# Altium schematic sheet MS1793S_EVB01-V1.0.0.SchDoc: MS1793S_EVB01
size A4; Date: 2018-06-01; Author: Wang QB; Revision: V1.0; SheetNumber: 1; SheetTotal: 1; PageSetup: Record=PageOptions¦CenterHorizontal=True¦CenterVertical=True¦PrintScale=1.00¦XCorrection=1.00¦YCorrection=1.00¦PrintKind=0¦BorderSize=5000000¦LeftOffset=0¦BottomOffset=0¦Orientation=2¦PaperLength=1000¦PaperWidth=1000¦Scale=100¦PaperSource=7¦PrintQuality=-3¦MediaType=1¦DitherType=10¦PrintScaleMode=1¦PaperKind=A4¦PaperIndex=9
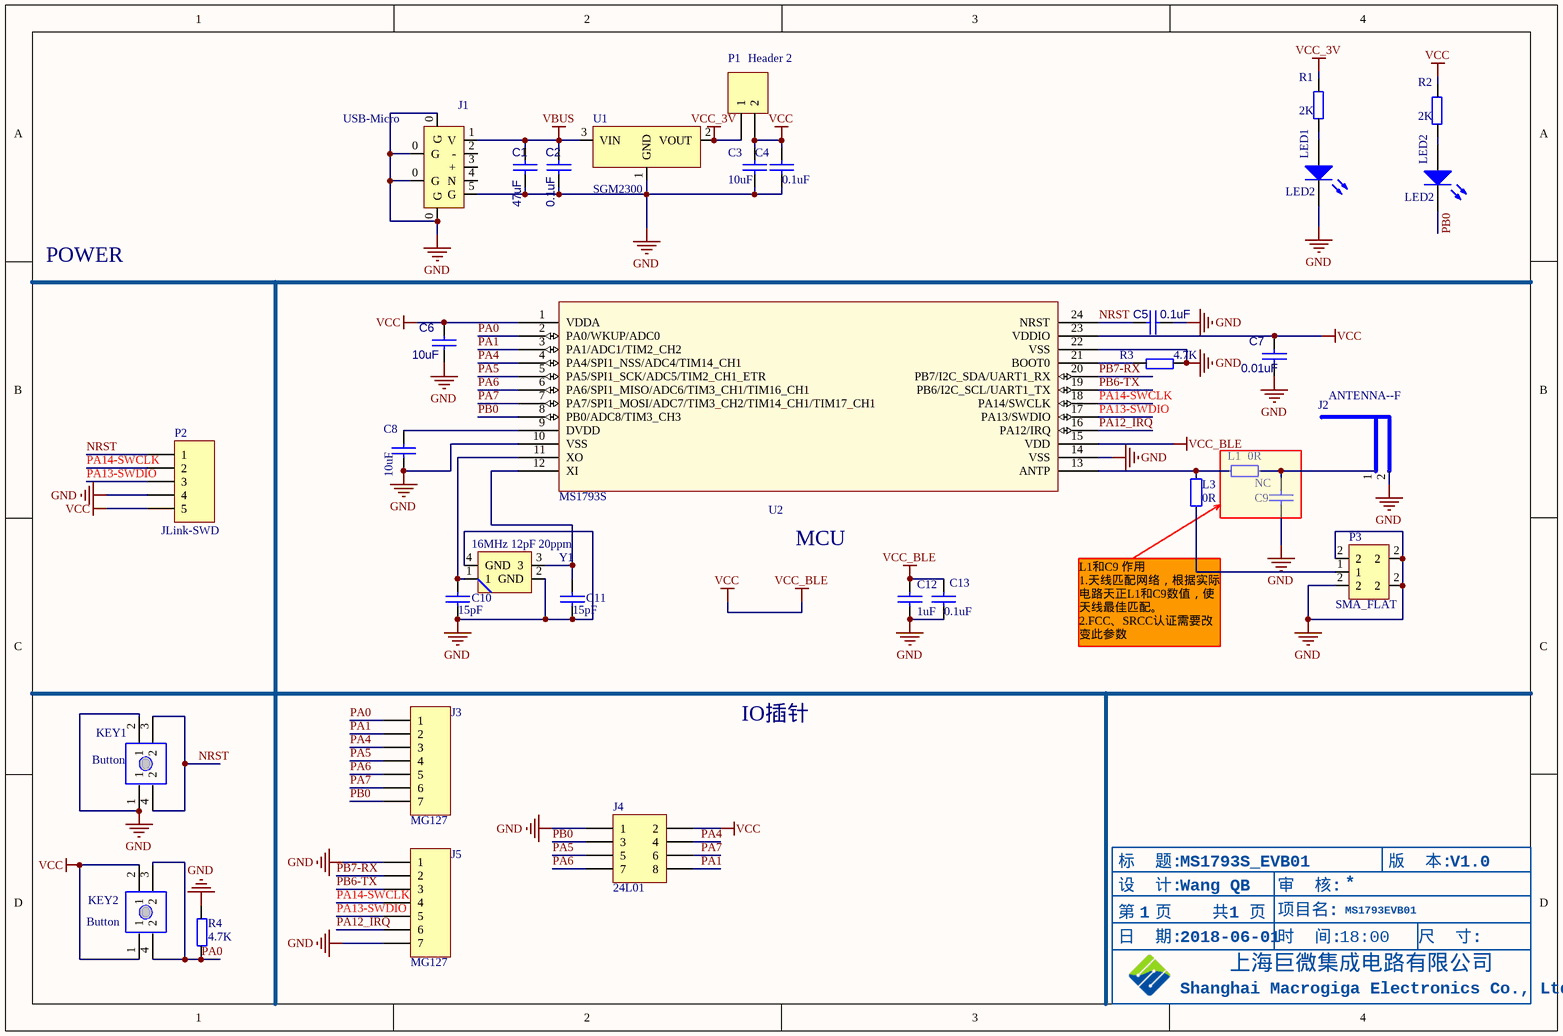
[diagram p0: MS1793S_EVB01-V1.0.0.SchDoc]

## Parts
C1  47uF  [c0603]
C2  0.1uF  [c0603]
C3  10uF  [C0603]
C4  0.1uF  [C0402]
C5  0.1uF  [C0402]
C6  10uF  [C0402]
C7  0.01uF  [C0402]
C8  10uF  [C0402]
C9  NC  [C0402]
C10  15pF  [C0402]
C11  15pF  [C0402]
C12  1uF  [C0402]
C13  0.1uF  [C0402]
J1  USB-Micro  [USB-MICRO]
J2  ANTENNA--F  [ANT-2]
J3  MG127  [HDR1X7]
J4  24L01  [HDR2X4]
J5  MG127  [HDR1X7]
KEY1  Button  [SW_DIP]
KEY2  Button  [SW_DIP]
L1  0R  [R0402]
L3  0R  [R0402]
LED1  LED2  [LED_0603]
LED2  LED2  [LED_0603]
P1  Header 2  [HDR1X2]
P2  JLink-SWD  [HDR1X5]
P3  SMA_FLAT  [SMA-KWE]
R1  2K  [R0402]
R2  2K  [R0402]
R3  4.7K  [R0402]
R4  4.7K  [R0402]
U1  SGM2300
U2  MS1793S  [TSSOP-24]
Y1  16MHz 12pF 20ppm  [XT3225]

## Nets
GND: C1.2 C2.2 C3.2 C4.2 C5.1 C6.2 C7.2 C8.2 C9.2 C10.2 C11.2 C12.2 C13.2 J1.0(G) J1.5(G) J2.2 J4.1 J5.1 J5.7 KEY1.1 KEY1.2(1) LED1.2(K) P2.4 P3.2 R3.2 R4.2 U1.1(GND) U2.10(VSS) U2.14(VSS) U2.22(VSS) Y1.2(GND) Y1.4(GND)
VBUS: C1.1 C2.1 J1.1(V) U1.3(VIN)
VCC: C3.1 C4.1 C6.1 C7.1 C12.1 C13.1 J4.2 KEY2.1 KEY2.2(1) P1.2 P2.5 R2.1 U2.1(VDDA) U2.15(VDD) U2.23(VDDIO)  [also labelled VCC_BLE]
VCC_3V: P1.1 R1.1 U1.2(VOUT)
NRST: C5.2 KEY1.3(2) KEY1.4(2) P2.1 U2.24(NRST)
PA0: J3.1 KEY2.3(2) KEY2.4(2) R4.1 U2.2(PA0/WKUP/ADC0)
PA1: J3.2 J4.8 U2.3(PA1/ADC1/TIM2_CH2)
PA4: J3.3 J4.4 U2.4(PA4/SPI1_NSS/ADC4/TIM14_CH1)
PA5: J3.4 J4.5 U2.5(PA5/SPI1_SCK/ADC5/TIM2_CH1_ETR)
PA6: J3.5 J4.7 U2.6(PA6/SPI1_MISO/ADC6/TIM3_CH1/TIM16_CH1)
PA7: J3.6 J4.6 U2.7(PA7/SPI1_MOSI/ADC7/TIM3_CH2/TIM14_CH1/TIM17_CH1)
PA12_IRQ: J5.6 U2.16(PA12/IRQ)
PA13-SWDIO: J5.5 P2.3 U2.17(PA13/SWDIO)
PA14-SWCLK: J5.4 P2.2 U2.18(PA14/SWCLK)
PB0: J3.7 J4.3 LED2.2(K) U2.8(PB0/ADC8/TIM3_CH3)
PB6-TX: J5.3 U2.19(PB6/I2C_SCL/UART1_TX)
PB7-RX: J5.2 U2.20(PB7/I2C_SDA/UART1_RX)
NetC8_1: C8.1 U2.9(DVDD)
NetC9_1: C9.1 J2.1 L1.1
NetC10_1: C10.1 U2.11(XO) Y1.1
NetC11_1: C11.1 U2.12(XI) Y1.3
NetL1_2: L1.2 L3.1 U2.13(ANTP)
NetL3_2: L3.2 P3.1
NetLED1_1: LED1.1(A) R1.2
NetLED2_1: LED2.1(A) R2.2
NetR3_1: R3.1 U2.21(BOOT0)

Not connected (* = marked no-connect by the designer): J1 2(-) 3(+) 4(N)

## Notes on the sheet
- POWER
- MCU
- L1和C9 作用
  1.天线匹配网络，根据实际电路天正L1和C9数值，使天线最佳匹配。
  2.FCC、SRCC认证需要改变此参数
- IO插针

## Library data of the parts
C1-C13 = CAP: Capacitor
J2 = ANT
J3 J5 = Header 7: Header, 7-Pin
J4 = Header 4X2: Header, 4-Pin, Dual row
KEY1 KEY2 = KEY-4: PCB DECAL: KEY; value: AUTO
L1 L3 = Res2: Resistor
LED1 LED2 = LED2: Typical RED, GREEN, YELLOW, AMBER GaAs LED
P1 = Header 2: Header, 2-Pin
P2 = Header 5: Header, 5-Pin
R1-R4 = R
U2 = MS1793S: BLE
Y1 = XTAL3225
